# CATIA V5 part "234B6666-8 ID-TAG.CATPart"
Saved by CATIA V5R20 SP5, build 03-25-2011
Part number: 234B6666-8 ID-TAG
Publications: "Lay up top of ID tag"
Bounding box of the stored display mesh (mm): x 31611.529 to 31624.209, y -11291.705 to -11284.906, z 5399.482 to 5412.613
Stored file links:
  C:\Users\rem1927\Desktop\Current Explicit Composite Demo\234B6666-8 ID-TAG.CATPart
  C:\Users\rem1927\Desktop\Current Explicit Composite Demo\234B5678-1 Composite Product.CATProduct
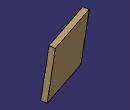
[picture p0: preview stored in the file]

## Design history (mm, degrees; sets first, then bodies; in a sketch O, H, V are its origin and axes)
Set1
  Offset1: Offset DatumSurface1, Length 0
  Point1: type OnSurface, Support Offset1, Length 179.777, Direction (-0.8747, 0.4614, -0.1486)
  Line1: type PtDir, RefPoint Point1, Direction edge of Offset1, Support Offset1, Start 0, End 12.7
  CurvePar1: Offset Line1, Support Offset1, Offset2 0, Offset1 12.7
  Line2: type PtPt, FirstPoint vertex of Line1, SecondPoint vertex of CurvePar1
  Line3: type PtPt, FirstPoint Point1, SecondPoint vertex of CurvePar1
  Join1: Elements (CurvePar1; Line3; Line1; Line2)
  CurvePar2: Offset Join1, Support Offset1, Offset2 0, Offset1 1.27
  Split1: ToCut Offset1, Cutting Join1
Set2
  DatumSurface1 "Layup Surface above Pass Through": linked copy from another document
Set3
  Extract1 "Top of ID surf": ExtractElem face of ThickSurface1
  Split2: ToCut {split ToCut Offset1, Cutting Join1}, Cutting CurvePar2
  Line4: type PtPt, FirstPoint vertex [face of CurvePar2 | face of CurvePar2], SecondPoint vertex [face of ThickSurface1]
  Line5: type PtPt, FirstPoint vertex [face of ThickSurface1], SecondPoint vertex [face of CurvePar2 | face of CurvePar2]
  Line6: type PtPt, FirstPoint vertex [face of CurvePar2 | face of CurvePar2], SecondPoint vertex [face of ThickSurface1]
  Line7: type PtPt, FirstPoint vertex [face of ThickSurface1], SecondPoint vertex [face of CurvePar2 | face of CurvePar2]
  Boundary1: Boundary edge of Extract1
  Boundary2: Boundary edge of Extract1
  Boundary3: Boundary edge of Extract1
  Boundary4: Boundary edge of Extract1
  Boundary5: Boundary edge of Split2
  Boundary6: Boundary edge of Split2
  Boundary7: Boundary edge of Split2
  Boundary8: Boundary edge of Split2
  Loft1: Sections (Line6; Line7), Guides (Boundary4; Boundary8)
  Loft2: Sections (Line6; Line4), Guides (Boundary3; Boundary7)
  Loft3: Sections (Line4; Line5), Guides (Boundary6; Boundary2)
  Loft4: Sections (Line7; Line5), Guides (Boundary1; Boundary5)
  Join2 "Lay up top of ID tag": Elements (Split2; Loft3; Loft2; Loft1; Loft4; Extract1)
Body1 "Part ID Tag" (main body)
  ThickSurface1: BotOffset 0, Surface Split1, TopOffset 1.27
